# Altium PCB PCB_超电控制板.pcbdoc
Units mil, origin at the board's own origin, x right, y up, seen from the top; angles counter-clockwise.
Board outline 3640 x 2780 mil, 2 copper layers (Top Layer, Bottom Layer); 100 components, 60 nets, 308 pads, 246 vias.
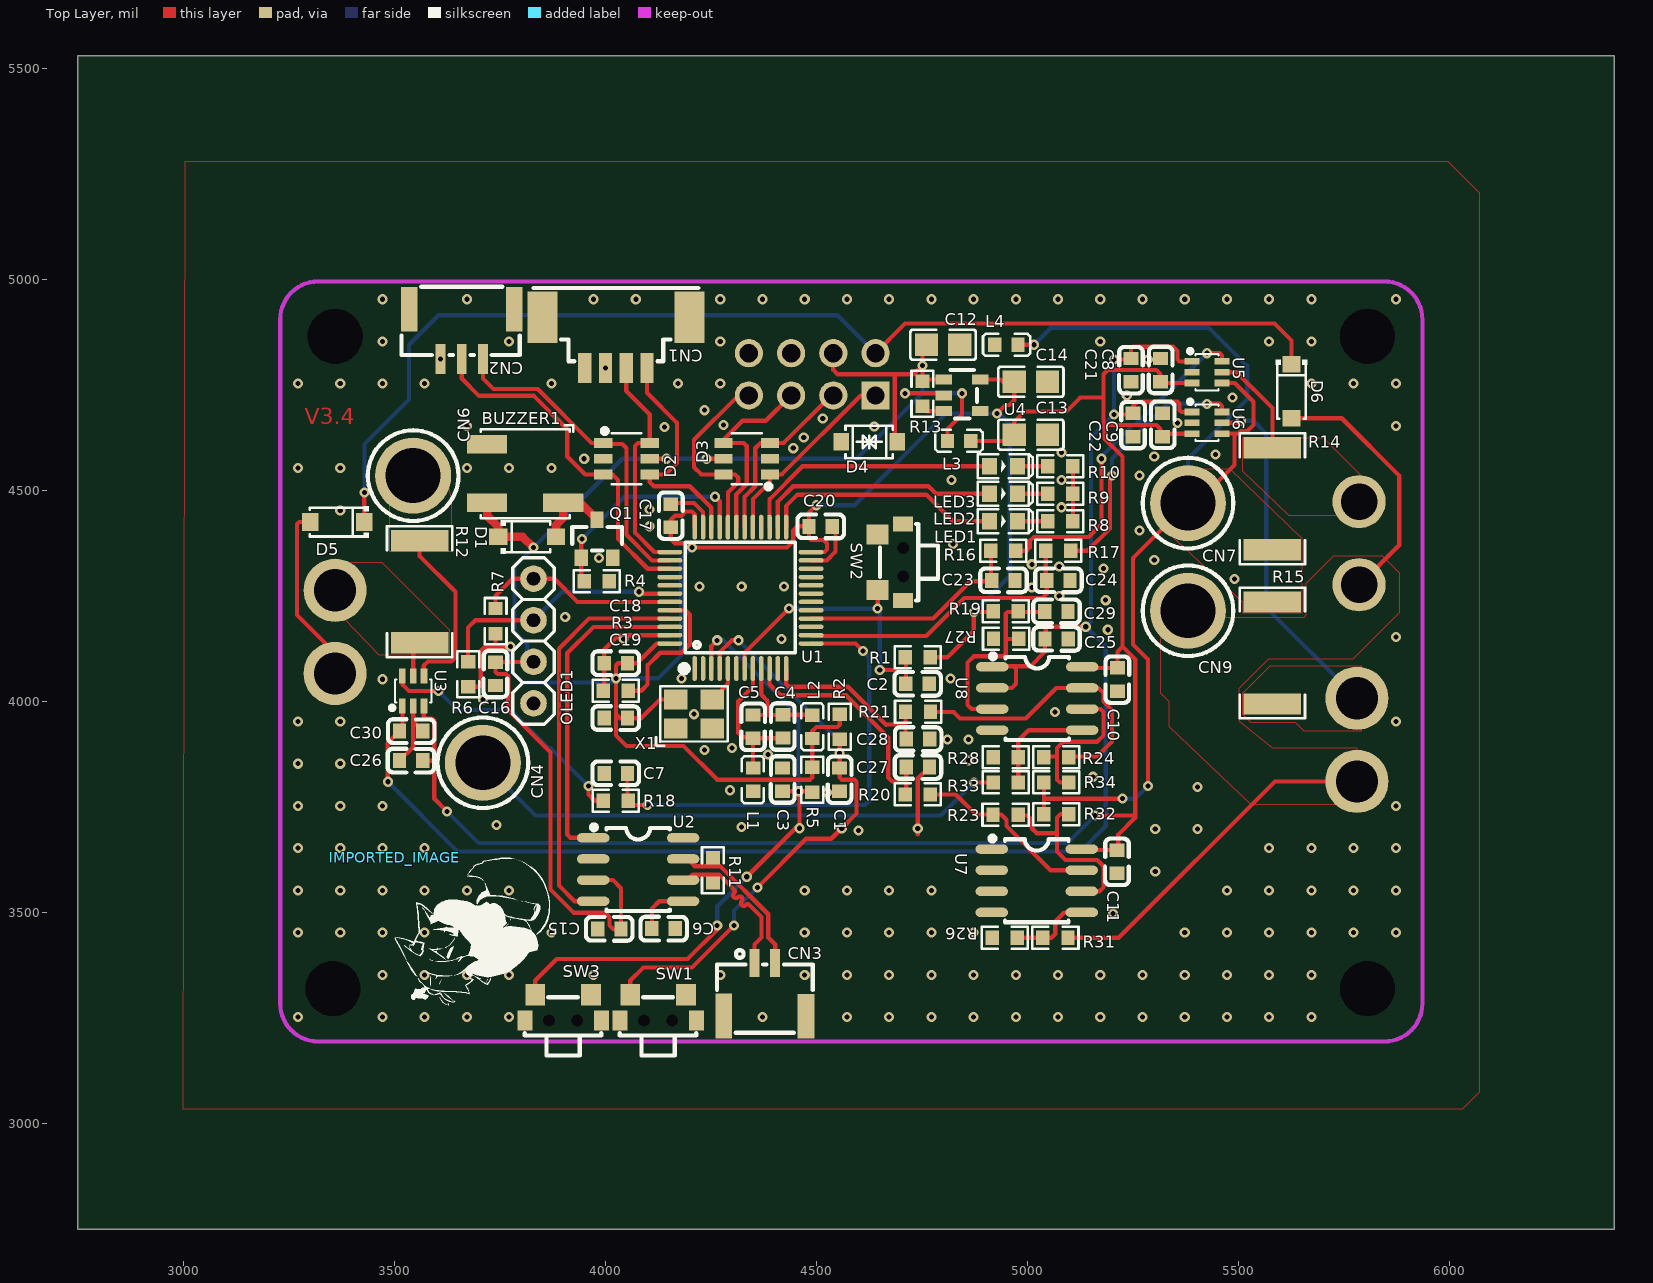
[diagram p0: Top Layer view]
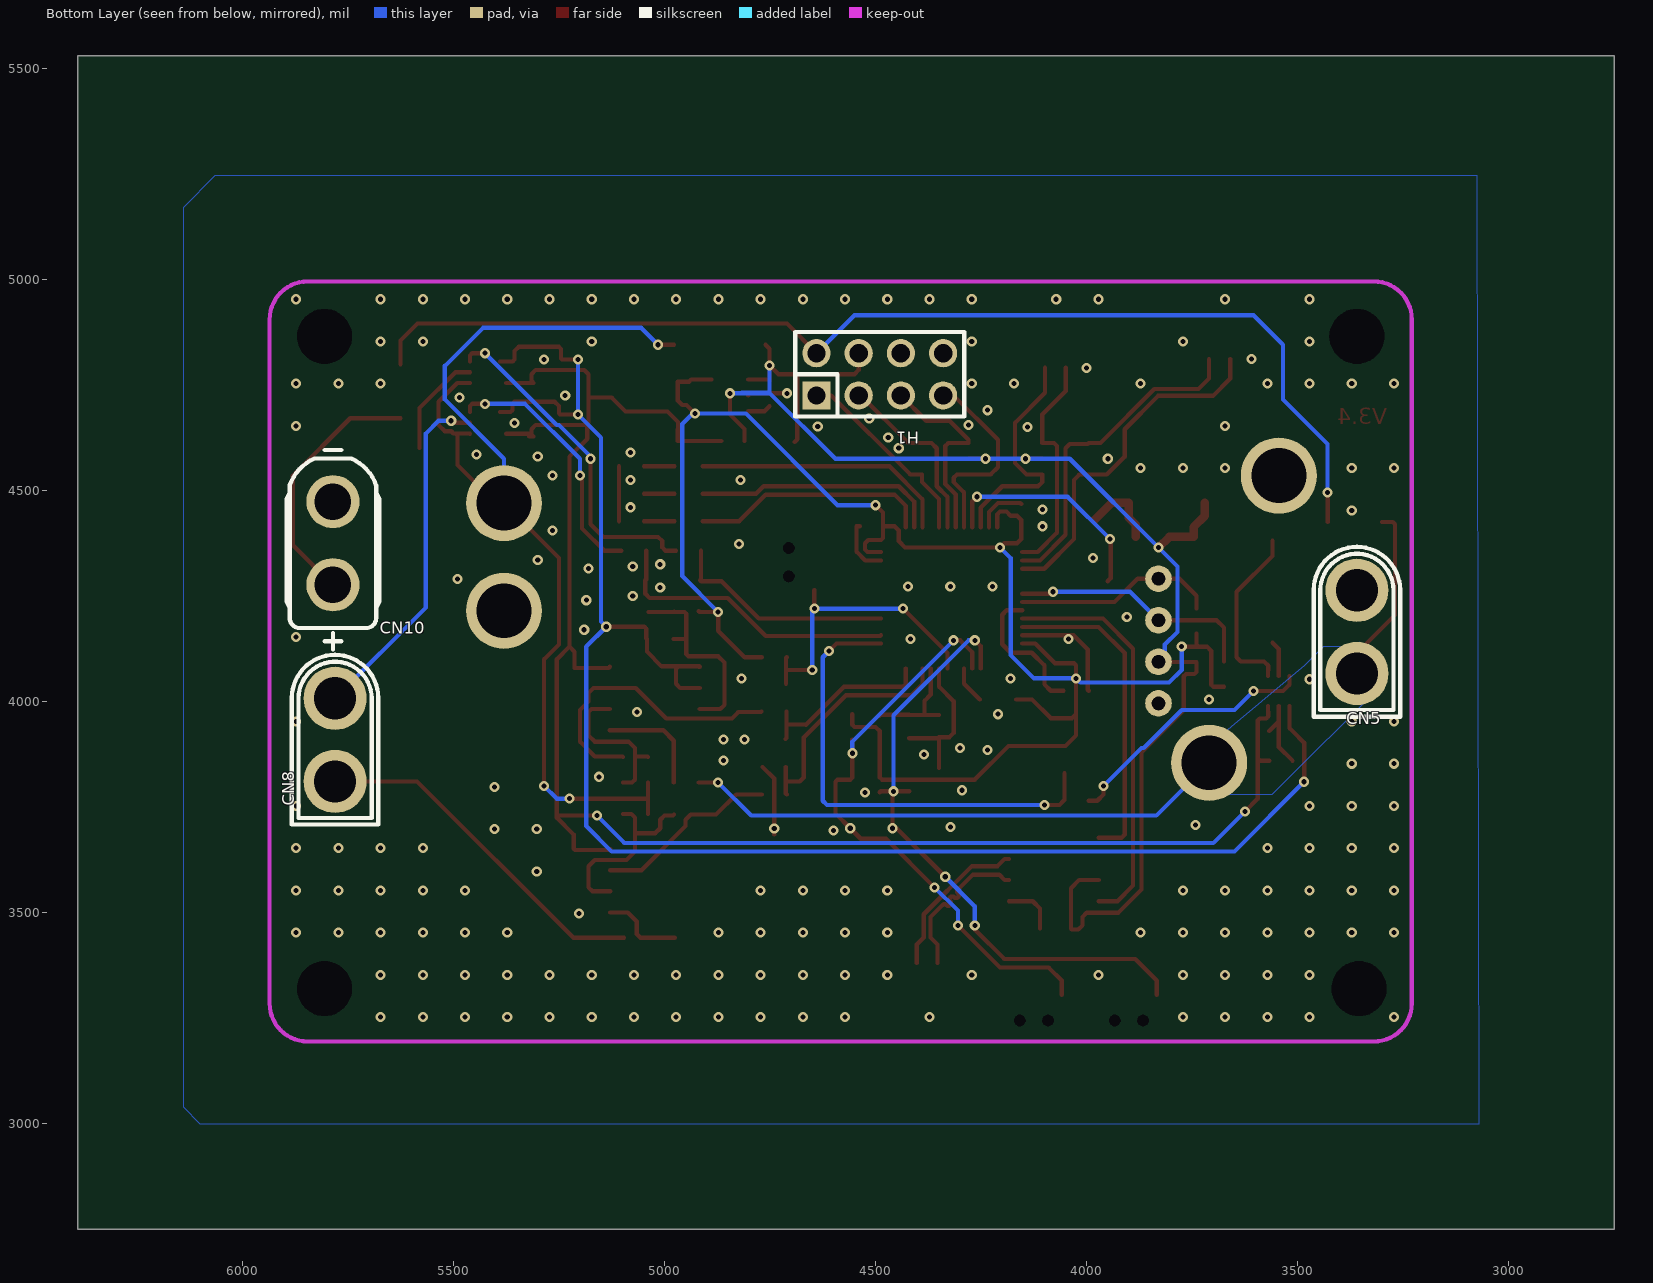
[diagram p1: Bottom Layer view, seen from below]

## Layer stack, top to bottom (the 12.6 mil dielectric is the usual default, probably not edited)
Top Layer: signal copper (thickness not stored)
Dielectric: dielectric 12.6, FR-4, Dk 4.8
Bottom Layer: signal copper (thickness not stored)

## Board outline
6390,2750 2750,2750 2750,5530 6390,5530
cut-out: 3420,3320 ccw(c3355,3320) 3290,3320 ccw(c3355,3320)
cut-out: 3425,4865 ccw(c3360,4865) 3295,4865 ccw(c3360,4865)
cut-out: 5870,4865 ccw(c5805,4865) 5740,4865 ccw(c5805,4865)
cut-out: 5870,3320 ccw(c5805,3320) 5740,3320 ccw(c5805,3320)

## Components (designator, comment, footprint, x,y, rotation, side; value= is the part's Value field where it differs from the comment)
BUZZER1 "MLT-5020" BUZ-SMD_3P-L5.2-W5.2-P3.50-BR 3810,4540 r90 top
C1 "1nf" C0603 4555,3815 r90 top
C2 "1uf" C0603 4739.39,4042.16 r180 top
C3 "1nf" C0603 4420,3815 r270 top
C4 "1nf" C0603 4420.4,3941 r90 top
C5 "0.1uf" C0603 4350,3940.7 r90 top
C6 "0.1uf" C0603 4137.8,3462.2 r180 top
C7 "330pF" C0603 4025,3830 r0 top
C8 "0.1u" C0603 5315,4785 r270 top
C9 "0.1u" C0603 5320,4655 r270 top
C10 "0.1u" C0603 5212.8,4052.2 r90 top
C11 "0.1u" C0603 5211.79,3620.61 r90 top
C12 "22u" C0805 4800,4845 r0 top
C13 "22u" C0805 5007.8,4632.2 r0 top
C14 "22u" C0805 5007.8,4757.2 r0 top
C15 "0.1u" C0603 4009.5,3461.7 r0 top
C16 "0.1u" C0603 3740,4065.7 r90 top
C17 "0.1u" C0603 4155,4440 r270 top
C18 "0.1u" C0603 4025,4090.7 r0 top
C19 "0.1u" C0603 4025,3960.7 r0 top
C20 "0.1u" C0603 4510,4415 r180 top
C21 "0.1u" C0603 5245,4785 r90 top
C22 "0.1u" C0603 5250,4655 r90 top
C23 "330pF" C0603 4942.8,4287.2 r180 top
C24 "330pF" C0603 5072.8,4287.2 r180 top
C25 "330pF" C0603 5069,4148.4 r0 top
C26 "0.1u" C0603 3540,3860 r0 top
C27 "330pF" C0603 4740,3845 r180 top
C28 "330pF" C0603 4740.56,3911.24 r180 top
C29 "330pF" C0603 5068.2,4213.7 r180 top
C30 "0.1u" C0603 3540,3930 r180 top
CN1 "1.25-4PWB" CONN-SMD_1.25-4PWB 4025,4850 r180 top
CN2 "GH1.25-3PWBPZ" CONN-SMD_GH1.25-3PWBPZ 3660,4870 r180 top
CN3 "GH1.25-2PWBPZ" CONN-SMD_GH1.25-2PWBPZ 4377.79,3317.89 r0 top
CN4 "m3焊盘" M3焊盘 3710,3855 r90 top
CN5 "XT30U-M" CONN-TH_XT30U-M 3360.01,4165 r90 bottom
CN6 "m3焊盘" M3焊盘 3545,4535 r90 top
CN7 "m3焊盘" M3焊盘 5380,4470 r0 top
CN8 "XT30U-M" CONN-TH_XT30U-M 5780.01,3909.3 r90 bottom
CN9 "m3焊盘" M3焊盘 5380,4215 r0 top
CN10 "XT30" CONN-TH_XT30UPB-F 5785.02,4375 r90 bottom
D1 "贴片二极管/JSPI3100A/SOD-123FL[捷捷微]" SOD-123F_L2.7-W1.6-LS3.8-RD 3815,4390 r0 top
D2 "IP4220CZ6" SOT-23-6_L2.9-W1.6-P0.95-LS2.7-BL 4050,4575 r270 top
D3 "IP4220CZ6" SOT-23-6_L2.9-W1.6-P0.95-LS2.7-BL 4335,4575 r90 top
D4 "SMFJ5.0CA" SOD-123_L2.8-W1.8-LS3.7-BI 4625,4615 r180 top
D5 "DSK310_C713648" SOD-123_L2.7-W1.8-LS3.7-RD 3365,4425 r180 top
D6 "DSK310_C713648" SOD-123_L2.7-W1.8-LS3.7-RD 5625,4735 r270 top
H1 "PZ254V-12-8P" HDR-TH_8P-P2.54-V-M-R2-C4-S2.54 4490,4775 r180 bottom
IMPORTED_IMAGE "IMPORTED_IMAGE" IMPORTED_IMAGE 3501,3630 r0 top
L1 "1m" L0603 4350,3815 r90 top
L2 "1m" L0603 4490.03,3940 r270 top
L3 "1m" L0603 4837.82,4617.2 r0 top
L4 "1m" L0603 4950,4845 r180 top
LED1 "LED-0603_R" LED0603_RED 4942.8,4427.2 r0 top
LED2 "LED-0603_G" LED0603_RED 4942.83,4492.17 r0 top
LED3 "LED-0603_B" LED0603_RED 4942.83,4557.17 r0 top
OLED1 "0.96OLED_4P_MODULE_JX" 排针2.54单排4PIN 3830,3995.68 r90 top
Q1 "2N7002" SOT-23_L2.9-W1.3-P0.95-LS2.4-BR 3980.53,4385.52 r270 top
R1 "10k" R0603 4740,4105 r180 top
R2 "10k" R0603 4555,3940 r90 top
R3 "1k" R0603 4025,4025.7 r180 top
R4 "10k" R0603 3980,4285 r180 top
R5 "10k" R0603 4490,3815 r90 top
R6 "10k" R0603 3675,4065 r90 top
R7 "10k" R0603 3740,4190.68 r90 top
R8 "100" R0603 5077.8,4427.2 r0 top
R9 "100" R0603 5077.8,4492.2 r0 top
R10 "100" R0603 5077.8,4557.2 r0 top
R11 "120" R0603 4255,3600 r270 top
R12 "2mΩ" R2512 3560,4260 r270 top
R13 "10k" R0603 4751.1,4728.9 r90 top
R14 "2mΩ" R2512 5580,4480 r90 top
R15 "2mΩ" R2512 5580,4115 r270 top
R16 "100" R0603 4942.8,4357.2 r0 top
R17 "100" R0603 5072.8,4357.2 r0 top
R18 "100" R0603 4025,3765 r180 top
R19 "2k" R0603 4948.2,4213.7 r0 top
R20 "100" R0603 4740,3780 r0 top
R21 "100" R0603 4740.56,3976.24 r0 top
R23 "3k3" R0603 4947.8,3732.2 r0 top
R24 "3k3" R0603 5068.3,3868.4 r180 top
R26 "3k3" R0603 4946.09,3440.61 r0 top
R27 "2k" R0603 4949,4148.4 r180 top
R28 "3k3" R0603 4948.3,3868.4 r0 top
R31 "68k" R0603 5066.09,3440.61 r180 top
R32 "68k" R0603 5068.3,3733.4 r180 top
R33 "68k" R0603 4948.3,3808.4 r0 top
R34 "68k" R0603 5068.3,3808.4 r0 top
SW1 "TS24CA" SW-SMD_TS24CA#1 4125,3275 r180 top
SW2 "TS24CA" SW-SMD_TS24CA#2 4675,4330 r270 top
SW3 "TS24CA" SW-SMD_TS24CA#1 3899.96,3275.01 r180 top
U1 "STM32F334C8T6" LQFP-48_L7.0-W7.0-P0.50-LS9.0-BL 4320,4245.68 r0 top
U2 "TJA1050T/CM,118" SOIC-8_L5.0-W4.0-P1.27-LS6.0-BL 4077.8,3602.2 r270 top
U3 "INA199A2DCKR" SOT-363_L2.0-W1.3-P0.65-LS2.1-BR 3545,4025 r270 top
U4 "RT9193-33" SOT-23-5_L2.9-W1.6-P0.95-LS2.8-BL 4845,4725 r270 top
U5 "INA199A2DCKR" SOT-363_L2.0-W1.3-P0.65-LS2.1-BR 5424.99,4780.01 r180 top
U6 "INA199A2DCKR" SOT-363_L2.0-W1.3-P0.65-LS2.1-BR 5424.99,4660.01 r180 top
U7 "GS8552-SR" SOIC-8_L5.0-W4.0-P1.27-LS6.0-BL 5021.79,3575.61 r270 top
U8 "GS8552-SR" SOIC-8_L5.0-W4.0-P1.27-LS6.0-BL 5022.8,4007.2 r270 top
X1 "8MHz" OSC-SMD_4P-L3.2-W2.5-BL 4210,3970.68 r0 top

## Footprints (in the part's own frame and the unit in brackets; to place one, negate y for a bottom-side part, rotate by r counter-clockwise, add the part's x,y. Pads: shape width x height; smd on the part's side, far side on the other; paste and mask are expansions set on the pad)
BUZ-SMD_3P-L5.2-W5.2-P3.50-BR [mm]
  rect 1.12x2.425 smd paste+0 mask+0.051: 1(1.75,2.288) 2(-1.75,2.288) 3(-1.75,-2.288)
  silkscreen extent -2.68,-2.9 2.9,2.68
C0603 [mm]
  rect 0.8x0.9 smd paste+0 mask+0.051: 1(-0.7,0) 2(0.7,0)
  silkscreen extent -1.41,-0.71 1.39,0.72
C0805 [mm]
  rect 1.41x1.35 smd paste-100 mask+0.051: 1(-1,0) 2(1,0)
  silkscreen extent -1.96,-0.9 1.96,0.9
CONN-SMD_1.25-4PWB [mm]
  rect 0.8x1.8 smd paste+0 mask+0.05: 1(-1.875,1.516) 2(-0.625,1.516) 3(0.625,1.516) 4(1.875,1.516)
  rect 1.8x3.1 smd paste+0 mask+0.05: 5(-4.425,-1.516) 6(4.425,-1.516)
  silkscreen extent -4.95,-3.28 4.95,1.12
CONN-SMD_GH1.25-2PWBPZ [mm]
  rect 0.6x1.7 smd paste+0 mask+0.051: 1(-0.625,1.602) 2(0.625,1.602)
  rect 1x2.7 smd paste+0 mask+0.051: 3(2.475,-1.602) 4(-2.475,-1.598)
  silkscreen extent -2.88,-2.6 2.88,2.37
CONN-SMD_GH1.25-3PWBPZ [mm]
  rect 0.6x1.8 smd paste+0 mask+0.05: 1(-1.27,1.501) 2(0,1.501) 3(1.27,1.501)
  rect 1x2.7 smd paste+0 mask+0.05: 4(-3.164,-1.501) 5(3.164,-1.501)
  silkscreen extent -3.49,-2.85 3.62,1.25
CONN-TH_XT30U-M [mm]
  round 3.8 hole 2.54 paste+0 mask+0.05: 1(-2.5,0) 2(2.5,0)
  silkscreen extent -5.1,-2.6 5.11,2.6
CONN-TH_XT30UPB-F [mm]
  round 3.2 hole 2.2 paste+0 mask+0.051: 1(-2.5,0) 2(2.5,0)
  silkscreen extent -6.4,-2.8 5.6,2.8
HDR-TH_8P-P2.54-V-M-R2-C4-S2.54 [mm]
  rect 1.7x1.7 hole 1.1 paste+0 mask+0.051: 1(-3.81,-1.27)
  round 1.7 hole 1.1 paste+0 mask+0.051: 2(-3.81,1.27) 3(-1.27,-1.27) 4(-1.27,1.27) 5(1.27,-1.27) 6(1.27,1.27) 7(3.81,-1.27) 8(3.81,1.27)
  silkscreen extent -5.08,-2.54 5.08,2.54
IMPORTED_IMAGE [mil]
  silkscreen extent 0,-350 368,0
L0603 [mm]
  rect 0.8x0.864 smd paste-100 mask+0.051: 1(-0.7,0) 2(0.7,0)
  silkscreen extent -1.42,-0.65 1.41,0.67
LED0603_RED [mm]
  rect 0.9x1 smd paste+0 mask+0.051: 1(-0.85,0) 2(0.85,0)
  silkscreen extent -1.54,-0.73 1.75,0.73
LQFP-48_L7.0-W7.0-P0.50-LS9.0-BL [mm]
  oval 0.27x1.5 smd paste+0 mask+0.05: 1(-2.75,-4.25) 2(-2.25,-4.25) 3(-1.75,-4.25) 4(-1.25,-4.25) 5(-0.75,-4.25) 6(-0.25,-4.25) 7(0.25,-4.25) 8(0.75,-4.25) 9(1.25,-4.25) 10(1.75,-4.25) 11(2.25,-4.25) 12(2.75,-4.25) 25(2.75,4.25) 26(2.25,4.25) 27(1.75,4.25) 28(1.25,4.25) 29(0.75,4.25) 30(0.25,4.25) 31(-0.25,4.25) 32(-0.75,4.25) 33(-1.25,4.25) 34(-1.75,4.25) 35(-2.25,4.25) 36(-2.75,4.25)
  oval 1.5x0.27 smd paste+0 mask+0.05: 13(4.25,-2.75) 14(4.25,-2.25) 15(4.25,-1.75) 16(4.25,-1.25) 17(4.25,-0.75) 18(4.25,-0.25) 19(4.25,0.25) 20(4.25,0.75) 21(4.25,1.25) 22(4.25,1.75) 23(4.25,2.25) 24(4.25,2.75) 37(-4.25,2.75) 38(-4.25,2.25) 39(-4.25,1.75) 40(-4.25,1.25) 41(-4.25,0.75) 42(-4.25,0.25) 43(-4.25,-0.25) 44(-4.25,-0.75) 45(-4.25,-1.25) 46(-4.25,-1.75) 47(-4.25,-2.25) 48(-4.25,-2.75)
  silkscreen extent -3.59,-4.46 3.3,3.34
M3焊盘 [mil]
  round 180 hole 130 paste+0 mask+1.97: 1(0.01,0)
  silkscreen extent -107,-107 107,107
OSC-SMD_4P-L3.2-W2.5-BL [mm]
  rect 1.4x1.2 smd paste+0 mask+0.051: 1(-1.1,-0.875) 2(1.1,-0.875) 3(1.1,0.875) 4(-1.1,0.875)
  silkscreen extent -2.29,-1.9 2.03,1.65
R0603 [mil]
  rect 31.75x34.02 smd paste-3937.01 mask+2: 1(-29.66,0) 2(29.66,0)
  silkscreen extent -55,-26 55,26
R2512 [mil]
  rect 50.49x136.06 smd paste-3937.01 mask+2: 1(-120.72,0) 2(120.72,0)
  silkscreen extent -155,-77 155,77
SOD-123_L2.7-W1.8-LS3.7-RD [mm]
  rect 1x1.1 smd paste+0 mask+0.051: 1(-1.627,0) 2(1.627,0)
  silkscreen extent -1.9,-0.94 1.65,0.95
SOD-123_L2.8-W1.8-LS3.7-BI [mm]
  rect 0.93x1.06 smd paste+0 mask+0.051: 1(1.685,0) 2(-1.685,0)
  silkscreen extent -1.43,-0.98 1.43,0.98
SOD-123F_L2.7-W1.6-LS3.8-RD [mm]
  rect 1.1x1 smd paste+0 mask+0.051: 1(-1.735,0) 2(1.735,0)
  silkscreen extent -1.6,-1 1.38,1
SOIC-8_L5.0-W4.0-P1.27-LS6.0-BL [mil]
  oval 22.38x76.78 smd paste+0 mask+2: 1(-75,-106.5) 2(-25,-106.5) 3(25,-106.5) 4(75,-106.5) 5(75,106.5) 6(25,106.5) 7(-25,106.5) 8(-75,106.5)
  silkscreen extent -106,-111 98,75
SOT-23-5_L2.9-W1.6-P0.95-LS2.8-BL [mm]
  rect 0.6x1 smd paste+0 mask+0.05: 1(-0.95,-1.1) 2(0,-1.1) 3(0.95,-1.1) 4(0.95,1.1) 5(-0.95,1.1)
  silkscreen extent -1.52,-0.7 1.4,0.89
SOT-23-6_L2.9-W1.6-P0.95-LS2.7-BL [mm]
  rect 0.6x1.1 smd paste+0 mask+0.051: 1(-0.95,-1.4) 2(0,-1.4) 3(0.95,-1.4) 4(0.95,1.4) 5(0,1.4) 6(-0.95,1.4)
  silkscreen extent -1.82,-1.45 1.54,0.89
SOT-23_L2.9-W1.3-P0.95-LS2.4-BR [mm]
  rect 1x0.8 smd paste+0 mask+0.051: 1(1.15,-0.95) 2(1.15,0.95) 3(-1.15,0)
  silkscreen extent -0.7,-1.5 0.7,1.5
SOT-363_L2.0-W1.3-P0.65-LS2.1-BR [mm]
  rect 0.9x0.4 smd paste+0 mask+0.051: 1(0.9,-0.65) 2(0.9,0) 3(0.9,0.65) 4(-0.9,0.65) 5(-0.9,0) 6(-0.9,-0.65)
  silkscreen extent -0.7,-1.4 1.14,1.1
SW-SMD_TS24CA#1 [mm]
  rect 0.9x1.2 smd paste+0 mask+0.051: 1(-2.3,0.775) 2(2.3,0.775)
  rect 1.2x1.3 smd paste+0 mask+0.051: 3(-1.675,-0.775) 4(1.675,-0.775)
  Multi-Layer board cut-out: -1.2,0.775 -1.165,0.623 -1.068,0.501 -0.928,0.434 -0.772,0.434 -0.632,0.501 -0.535,0.623 -0.5,0.775 -0.5,0.775 -0.535,0.927 -0.632,1.049 -0.772,1.116 -0.928,1.116 -1.068,1.049 -1.165,0.927 -1.2,0.775
  Multi-Layer board cut-out: 0.5,0.775 0.535,0.623 0.632,0.501 0.772,0.434 0.928,0.434 1.068,0.501 1.165,0.623 1.2,0.775 1.2,0.775 1.165,0.927 1.068,1.049 0.928,1.116 0.772,1.116 0.632,1.049 0.535,0.927 0.5,0.775
  silkscreen extent -2.3,-0.62 2.3,2.88
SW-SMD_TS24CA#2 [mm]
  rect 0.9x1.2 smd paste+0 mask+0.051: 1(-2.3,0.775) 2(2.3,0.775)
  rect 1.2x1.3 smd paste+0 mask+0.051: 3(-1.675,-0.775) 4(1.675,-0.775)
  Multi-Layer board cut-out: -0.85,1.125 -1.002,1.09 -1.124,0.993 -1.191,0.853 -1.191,0.697 -1.124,0.557 -1.002,0.46 -0.85,0.425 -0.85,0.425 -0.698,0.46 -0.576,0.557 -0.509,0.697 -0.509,0.853 -0.576,0.993 -0.698,1.09 -0.85,1.125
  Multi-Layer board cut-out: 0.85,1.125 0.698,1.09 0.576,0.993 0.509,0.853 0.509,0.697 0.576,0.557 0.698,0.46 0.85,0.425 0.85,0.425 1.002,0.46 1.124,0.557 1.191,0.697 1.191,0.853 1.124,0.993 1.002,1.09 0.85,1.125
  silkscreen extent -2.3,-0.62 2.3,2.88
排针2.54单排4PIN [mm]
  round 1.6 hole 0.8 slot 0.805 at 0 deg paste+0 mask+0.051: 1(0,0) 2(2.5,0) 3(5,0) 4(7.5,0)
  silkscreen extent -1.25,-1.25 8.75,1.25

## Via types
v1: diameter 24, hole 12, Top Layer to Bottom Layer, 242 vias
v2: diameter 24.02, hole 12.01, Top Layer to Bottom Layer, 4 vias

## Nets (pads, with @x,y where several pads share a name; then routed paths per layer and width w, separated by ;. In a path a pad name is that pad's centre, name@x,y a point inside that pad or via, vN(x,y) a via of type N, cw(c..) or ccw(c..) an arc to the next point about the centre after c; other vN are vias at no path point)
1.65V: C21.2 C22.2 C25.1 C30.2 U3.1 U5.1 U6.1 U8.1 U8.2 | length 4023.6
  Top Layer w10: v1(3485,3810) 3485,3902.56 C30.2 3519.41,3936.97 U3.1 ; U8.2 4962.8,4032.2 4972.8,4042.2 4972.8,4077.2 4966.56,4083.44 U8.1@4917.54,4083.44 ; U8.1 U8.1@4918.8,4082.2 ; 4966.6,4083.4 5006.6,4083.4 5041.5,4118.4 5041.5,4148.4 5042.8,4149.8 5042.8,4172.2 5047.8,4177.2 v1(5137.8,4177.2) ; v1(5205,4680) 5247.44,4680 C22.2 ; v1(5205,4810) 5242.44,4810 C21.2 5245,4835 5250,4840 5345,4840 5355,4830 5355,4810 5359.41,4805.59 U5.1 ; C22.2 5250,4700 5260,4710 5355,4710 5360,4705 5360,4690 5364.4,4685.6 ; 5364.4,4685.6 U6.1 5369.4,4685.6 5364.4,4685.6
  Bottom Layer w10: v1(3485,3810) 3650,3645 5125,3645 5185,3705 5185,4130 v1(5137.8,4177.2) 5150,4189.4 5150,4625 v1(5205,4680) v1(5205,4810)
3V3: C14.1 C17.2 C18.2 C19.2 C20.2 L2.2 R1.1 R2.2 R5.2 R6.1 R7.1 R19.1 U1.24 U1.36 U1.48 U4.5 X1.4 | length 4319.3
  Top Layer w10: R6.1 3699.7,4035.3 3705,4040 3705,4120 3715,4130 3735,4130 ; R7.1 3740,4135 3735,4130 ; v1(3775,4130) 3735,4130 ; U1.48 4121.7,4137.4 4075,4090.7 C18.2 4030,4090.7 4025,4085.7 4025,3970.7 ; X1.4 4129.4,4005.1 4085,3960.7 C19.2 4035,3960.7 4025,3970.7 ; U1.36 4211.7,4443.3 4205,4450 4190,4450 4180,4440 4165,4440 4155,4430 C17.2 4155,4385 4165,4375 4195,4375 v1(4205,4365) 4430,4365 4445,4380 4445,4405 4455,4415 C20.2 4482.44,4447.44 v1(4500,4465) ; C20.2 4482.4,4387.6 4487.4,4382.6 4517.4,4382.6 4525,4375 4525,4360 4519,4354 U1.24 ; R2.2 4555,3945 4550,3940 4500,3940 4490,3930 L2.2 R5.2 4490,3820 4485,3815 4265,3815 4185,3895 4050,3895 4025,3920 4025,3970.7 ; R1.1 4810,4105 4872.8,4167.8 v1(4872.8,4212.2) 4917.13,4212.2 R19.1@4918.58,4213.65 ; U4.5 4936.73,4762.4 4941.93,4757.2 C14.1 4968.43,4712.83 4957.8,4702.2 4947.8,4702.2 v1(4927.8,4682.2)
  Bottom Layer w10: v1(3775,4130) 3775,4075 3805,4045 4015,4045 v1(4025,4055) 4125,4055 4180,4110 4180,4340 v1(4205,4365) ; v1(4500,4465) 4590,4465 4807.2,4682.2 v1(4927.8,4682.2) 4932.8,4682.2 4957.8,4657.2 4957.8,4297.2 v1(4872.8,4212.2)
+5V: BUZZER1.2 C12.1 C15.2 C16.2 D1.1 D2.5 D3.5 D4.2 H1.4 L3.1 OLED1.2 R13.2 U2.3 U4.1 | length 3653
  Top Layer w10: C16.2@3740,4093.2 3740,4070 3745,4065 3765,4065 3770,4060 3770,3980 3870,3880 3870,3555 3925,3500 4000,3500 4010,3490 4010,3470 4020,3460 4035.36,3460 C15.2 ; C16.2 OLED1.2 ; U2.3 4017.8,3577.2 4037.11,3557.9 C15.2 ; D2.5 v1(4145,4575) ; v1(4240,4575) D3.5 ; H1.4 4540,4785 4550,4775 4730,4775 v1(4751.1,4796.1) ; 4685.34,4775 4685.34,4621 D4.2 ; R13.2 4751.1,4835.47 C12.1 ; R13.2 4754.9,4762.4 U4.1 ; L3.1@4810.2,4617.2 4810.2,4645.2 4845,4680 v1(4845,4730)
  Top Layer w20: BUZZER1.2 3719.9,4440.1 3746.7,4413.3 D1.1 3804.05,4390 v1(3829.53,4364.53)
  Bottom Layer w10: OLED1.2 3815,4109.1 3815,4135 3785,4165 3785,4320 v1(3829.53,4364.53) 4040,4575 v1(4145,4575) v1(4240,4575) ; v1@4238.65,4575 v1(4240,4575) ; v1(4751.1,4796.1) 4751.1,4730 v1(4845,4730) ; 4817.2,4730 4816.1,4731.1 4751.1,4731.1 4595,4575 v1(4240,4575)
ADC_ICUP: C7.2 R18.1 U1.13 | length 1135.6
  Top Layer w10: C7.2 4052.56,3767.1 R18.1 4064.66,3755 v1(4100,3755) ; U1.13 4592.59,4137.41 v1(4610,4120)
  Bottom Layer w10: v1(4100,3755) 4615,3755 4625,3765 4625,4105 v1(4610,4120)
ADC_IIN: C24.2 R17.1 U1.14 | length 703.1
  Top Layer w10: U1.14 4489.4,4155 4760,4155 4850,4245 5035,4245 5045.2,4255.2 C24.2 ; R17.1 5043.14,4289.3 C24.2
ADC_IOUT: C23.2 R16.1 U1.16 | length 537.6
  Top Layer w10: U1.16 4776.5,4196.5 4865,4285 4913,4285 C23.2 4913.1,4287.2 R16.1
ADC_VCC: C27.2 R20.1 U1.10 | length 575.8
  Top Layer w10: U1.10 4388.9,4041.1 4415,4015 4570,4015 4670,3915 4670,3820 4679.5,3810.5 4710.4,3810.5 ; R20.1 4712.44,3782.1 C27.2
ADC_VCUP: C28.2 R21.1 U1.12 | length 425.2
  Top Layer w10: U1.12 4428.3,4041.7 4435,4035 4575,4035 4665,3945 4710.9,3945.6 ; R21.1@4710.94,3976.28 4710.94,3913.38 C28.2@4713.05,3911.28
AVCC: C8.2 C9.2 C10.2 C11.2 C13.1 C26.2 L3.2 U3.3 U5.3 U6.3 U7.8 U8.8 | length 4253.9
  Top Layer w10: C26.2 3590,3860 3595,3865 ; U3.3 3570,3965 3575,3960 3590,3960 3595,3955 3595,3865 ; v1(3625,3740) 3595,3770 3595,3865 ; L3.2 4968.4,4617.2 C13.1 4967.8,4662.2 4992.8,4687.2 5092.2,4687.2 5125,4720 5180,4720 ; U7.8 5130.77,3648.21 C11.2 ; U8.8 5131.74,4079.76 C10.2 ; v1(5160,3730) 5250,3730 5255,3725 ; 5182.8,4657.2 5182.8,4622.2 5225,4580 5225,4130 ; C11.2 5215,3651.38 5215,3685 5255,3725 ; C10.2 5212.8,4117.8 5225,4130 ; 5225,4136.9 5225,4130 ; C8.2@5310,4754.4 5313.04,4757.44 C8.2 5315,4754.4 U5.3@5374.57,4754.4 ; C9.2@5315,4627.4 5315,4645 5305,4655 5185,4655 5180,4660 5180,4720 ; C8.2 5315,4775 5305,4785 5190,4785 5180,4775 5180,4720 ; C9.2 5310,4627.44 5316.96,4634.4 U6.3@5374.57,4634.4 ; 5225,4130 5255,4100 5255,3725
  Bottom Layer w10: v1(3625,3740) 3700,3665 5095,3665 v1(5160,3730)
BUZZER: Q1.1 R4.2 U1.33 | length 536.7
  Top Layer w10: v1(3945,4385) 3943.12,4383.12 Q1.1 3943.12,4292.22 R4.2 ; v1(4260,4485) 4270.79,4474.21 U1.33
  Bottom Layer w10: v1(3945,4385) 4045,4485 v1(4260,4485)
BUZZER1_3: BUZZER1.3 D1.2 Q1.3 | length 185.2
  Top Layer w20: D1.2 3883.3,4418.3 3900.1,4435.1 BUZZER1.3 ; BUZZER1.3 3940.22,4471.1 Q1.3
C4_1: C4.1 C5.1 L1.2 U1.8 | length 349.8
  Top Layer w10: U1.8 4349.5,4035.2 4315,4000.7 4315,3925.7 4325,3915.7 4350,3915.7 C5.1 4420.1,3913.1 C4.1 ; L1.2 C5.1
C6_2: C6.2 U2.5 | length 128.8
  Top Layer w10: C6.2 4110.24,3509.64 4127.8,3527.2 U2.5
C29_2: C29.2 R19.2 R27.1 U8.3 | length 479.7
  Top Layer w10: U8.3 4867.8,3982.2 4857.8,3992.2 4857.8,4092.2 4872.8,4107.2 4942.8,4107.2 4948.3,4112.7 4948.3,4207.7 4952.8,4212.2 4975.4,4212.2 R19.2@4976.6,4213.4 ; 4949.04,4148.44 R27.1 ; R19.2@4975.02,4212.2 C29.2@5037.8,4212.2
CAN_N: CN3.1 R11.2 U2.6 | length 377.5
  Top Layer w10: U2.6 4194.3,3577.2 4207.1,3590 4269.44,3590 4304.63,3554.77 cw(c4300.03,3550.18) 4304.63,3545.58 ccw(c4309.27,3541.03) 4313.82,3536.39 cw(c4318.42,3531.79) 4323.01,3536.39 cw(c4318.42,3531.79) 4323.01,3527.2 ccw(c4327.61,3522.6) 4332.21,3518 cw(c4336.8,3513.41) 4341.4,3518 4369.8,3489.65 4369.8,3441.05 4353.18,3424.43 CN3.1
CAN_P: CN3.2 R11.1 U2.7 | length 377.9
  Top Layer w10: U2.7 4194.3,3627.2 4211.31,3610.19 4251.31,3610.19 4271.86,3610.19 4385.78,3496.27 4385.78,3481.05 4385.78,3441.05 4402.4,3424.43 CN3.2
CAN_RX: U1.45 U2.4 | length 949.6
  Top Layer w10: U2.4 3927.2,3527.2 3890,3564.4 3890,4125 3961.5,4196.5 U1.45
CAN_TX: U1.46 U2.1 | length 762.8
  Top Layer w10: U2.1 3917.8,3677.2 3910,3685 3910,4115 3971.8,4176.8 U1.46
GND: BUZZER1.1 C1.1 C2.1 C3.1 C6.1 C7.1 C8.1 C9.1 C10.1 C11.1 C12.2 C13.2 C14.2 C15.1 C16.1 C17.1 C18.1 C19.1 C20.1 C21.1 C22.1 C23.1 C24.1 C25.2 C26.1 C27.1 C28.1 C29.1 C30.1 CN1.3 CN1.5 CN1.6 CN2.3 CN2.4 CN2.5 CN3.3 CN3.4 D2.2 D3.2 D4.1 H1.6 H1.8 L1.1 L4.2 OLED1.1 Q1.2 R3.2 R4.1 R8.2 R9.2 R10.2 R26.1 R27.2 R28.1 SW1.1 SW1.2 SW1.3 SW2.1 SW2.2 SW2.3 SW3.1 SW3.2 SW3.3 U1.23 U1.35 U1.47 U2.2 U2.8 U3.2 U4.2 U5.2 U6.2 U7.4 U8.4 X1.2 | length 1093.3
  Top Layer w10: C26.1 3545,3892.56 3545,3952.56 ; U3.2 3545,3952.56 ; C30.1 3545,3952.56 ; R3.2 3997.4,4027.8 C18.1 3997.4,4123.1 4031.4,4157.1 U1.47 ; C17.1 4157.44,4470 4210,4470 4231.42,4448.58 U1.35 ; U1.23 4524.3,4334.3 4545,4355 4545,4415 C20.1 ; v1(4710,4730) 4796.69,4730 U4.2 ; 4740,3685 v1(4740,3698.97) 4740,3817.44 C27.1 ; R8.2 R10.2
  other v1: 3272.2,3252.8 3272.2,3252.8 3472.2,3252.8 3572.2,3252.8 3672.2,3252.8 3772.2,3252.8 4372.2,3252.8 4572.2,3252.8 4672.2,3252.8 4772.2,3252.8 4872.2,3252.8 4972.2,3252.8 5072.2,3252.8 5172.2,3252.8 5272.2,3252.8 5372.2,3252.8 5472.2,3252.8 5572.2,3252.8 5672.2,3252.8 3472.2,3352.8 3572.2,3352.8 3672.2,3352.8 3772.2,3352.8 3972.2,3352.8 4272.2,3352.8 4472.2,3352.8 4572.2,3352.8 4672.2,3352.8 4772.2,3352.8 4872.2,3352.8 4972.2,3352.8 5072.2,3352.8 5172.2,3352.8 5272.2,3352.8 5372.2,3352.8 5472.2,3352.8 5572.2,3352.8 5672.2,3352.8 3272.2,3452.8 3372.2,3452.8 3472.2,3452.8 3572.2,3452.8 3672.2,3452.8 3772.2,3452.8 3872.2,3452.8 4472.2,3452.8 4572.2,3452.8 4672.2,3452.8 4772.2,3452.8 4872.2,3452.8 5372.2,3452.8 5472.2,3452.8 5572.2,3452.8 5672.2,3452.8 5772.2,3452.8 5872.2,3452.8 5202.36,3497.76 3272.2,3552.8 3372.2,3552.8 3472.2,3552.8 3572.2,3552.8 3672.2,3552.8 3772.2,3552.8 4472.2,3552.8 4572.2,3552.8 4672.2,3552.8 4772.2,3552.8 5472.2,3552.8 5572.2,3552.8 5672.2,3552.8 5772.2,3552.8 5872.2,3552.8 5302.36,3597.76 3272.2,3652.8 3372.2,3652.8 3472.2,3652.8 3572.2,3652.8 5572.2,3652.8 5672.2,3652.8 5772.2,3652.8 5872.2,3652.8 4600,3695 5302.36,3697.76 5402.36,3697.76 4322.2,3702.8 3742.2,3707.8 3272.2,3752.8 3372.2,3752.8 3472.2,3752.8 5872.2,3752.8 4525,3785 4295,3790 5402.36,3797.76 5155.14,3821.81 3272.2,3852.8 3372.2,3852.8 4860,3860 4385,3875 4235,3885 4300,3890 4810,3910 4860,3910 3272.2,3952.8 3372.2,3952.8 5872.2,3952.8 4210,3970 5065,3975 3710,4005 3472.2,4052.8 4817.67,4054.49 4180,4055 4417.67,4148.02 5872.2,4152.8 5190,4170 3905,4200 5185,4240 5075,4250 5010,4270 4223.01,4272.8 4323.01,4272.8 4423.01,4272.8 5180,4315 5075,4320 5010,4325 5300,4335 3985,4340 4823.01,4372.8 5265,4405 4105,4415 3372.2,4452.8 4105,4455 5080,4460 4820,4525 5080,4525 5265,4535 3272.2,4552.8 3372.2,4552.8 3672.2,4552.8 3772.2,4552.8 3872.2,4552.8 3950,4575 5300,4580 5445,4585 5080,4590 4445,4600 4470,4625 4140,4650 4636.98,4651.78 3672.2,4652.8 5872.2,4652.8 4280,4655 5355,4660 4515,4670 4235,4690 5485,4720 5235,4725 3272.2,4752.8 3372.2,4752.8 3472.2,4752.8 3572.2,4752.8 3872.2,4752.8 4172.2,4752.8 4272.2,4752.8 5672.2,4752.8 5772.2,4752.8 5872.2,4752.8 4000.4,4790.3 5285,4810 3610,4810.91 3472.2,4852.8 3772.2,4852.8 4272.2,4852.8 5172.2,4852.8 5572.2,4852.8 5672.2,4852.8 3472.2,4952.8 3672.2,4952.8 3972.2,4952.8 4072.2,4952.8 4272.2,4952.8 4372.2,4952.8 4472.2,4952.8 4572.2,4952.8 4672.2,4952.8 4772.2,4952.8 4872.2,4952.8 4972.2,4952.8 5072.2,4952.8 5172.2,4952.8 5272.2,4952.8 5372.2,4952.8 5472.2,4952.8 5572.2,4952.8 5672.2,4952.8 5872.2,4952.8
  other v2: 4042.68,4147.79
HRTIM1_CHA1: D3.1 H1.1 U1.29 | length 468.9
  Top Layer w10: U1.29 4349.53,4479.53 4390.12,4520.12 D3.1 4417.6,4537.6 4605,4725 H1.1
HRTIM1_CHA2: D3.3 H1.3 U1.30 | length 434.2
  Top Layer w10: U1.30 4329.84,4484.84 4355,4510 4355,4600 4367.4,4612.4 D3.3 4422.4,4612.4 4535,4725 H1.3
HRTIM1_CHB1: D3.4 H1.5 U1.31 | length 471.6
  Top Layer w10: U1.31 4310.16,4490.16 4335,4515 4335,4605 4327.6,4612.4 D3.4 4279.9,4619.9 4325,4665 4380,4665 H1.5
HRTIM1_CHB2: D3.6 H1.7 U1.32 | length 481
  Top Layer w10: U1.32 4290.5,4495.5 4315,4520 4315,4530 4307.4,4537.6 D3.6 4227.4,4537.6 4210,4555 4210,4620 4315,4725 H1.7
I2C_SCL: OLED1.3 R6.2 U1.42 | length 595
  Top Layer w10: R6.2 3675,4175 3692.5,4192.5 OLED1.3 ; v1(4080,4260) 4084.48,4255.52 U1.42
  Bottom Layer w10: OLED1.3 3897.5,4260 v1(4080,4260)
I2C_SDA: OLED1.4 R7.2 U1.43 | length 482.6
  Top Layer w10: R7.2 3740,4250.68 3780.28,4290.97 OLED1.4 ; OLED1.4 3879,4291 3934.2,4235.8 U1.43
KEY1: C1.2 R2.1 SW1.4 U1.4 | length 1424.5
  Top Layer w10: SW1.4 4059.05,3339.05 4090,3370 4205,3370 v1(4305,3470) ; U1.4 4270.8,4116.5 4299.3,4145 v2(4315,4145) ; v1(4360,3560) 4475,3675 4535,3675 v1(4560,3700) 4595,3735 4595,3810 4590,3815 4560,3815 4555,3820 C1.2 ; C1.2 v1(4555,3877.56) R2.1
  Bottom Layer w10: v1(4305,3470) 4305,3505 v1(4360,3560) ; v2(4315,4145) 4555,3905 v1(4555,3877.56)
KEY2: C3.2 R5.1 SW3.4 U1.3 | length 1527.9
  Top Layer w10: SW3.4@3834,3314 SW3.4 3834.01,3339.01 3885,3390 4195,3390 4265,3460 v1(4265,3470) ; U1.3 4251.1,4131.8 4264.3,4145 v2(4265,4145) ; v1(4335,3585) 4450,3700 v1(4460,3700) 4460,3784.87 v1(4457.43,3787.44) ; C3.2 v1(4457.43,3787.44) ; R5.1 4487.9,3787.44 v1(4457.43,3787.44)
  Bottom Layer w10: v1(4265,3470) 4265,3515 v1(4335,3585) ; v2(4265,4145) 4280,4145 4457.4,3967.6 v1(4457.43,3787.44)
L2_1: C4.2 C5.2 L2.1 U1.9 | length 257.7
  Top Layer w10: C5.2 C4.2 ; U1.9 4369.2,4016.5 4384,4001.7 4384,3968.4 ; C4.2@4420.4,3968.5 4487.5,3968.5 L2.1@4490.4,3965.6
LEDB: LED3.1 U1.27 | length 618.8
  Top Layer w10: U1.27 4388.9,4478.9 4467.17,4557.17 LED3.1
LEDG: LED2.1 U1.26 | length 595.4
  Top Layer w10: U1.26 4408.58,4473.58 4445,4510 4765,4510 4782.83,4492.17 LED2.1 ; LED2.1@4897.8,4492.2 LED2.1
LEDR: LED1.1 U1.25 | length 568.4
  Top Layer w10: U1.25 4428.27,4463.27 4455,4490 4760,4490 4822.8,4427.2 LED1.1
PGND: CN7.1 L4.1 R14.1 R15.1 R32.2 R34.1 U5.4 U6.4 | length 2520.3
  Top Layer w10: L4.1 v1(5015,4845) ; R32.2@5038.68,3733.44 R34.1@5038.68,3808.44 ; 5038.7,3769.9 v1(5225,3770) ; 5038.68,3771.88 5039,3772.2 ; v1(5285,3800) 5285,4100 5250,4135 5250,4340 CN7.1 ; CN7.1@5380,4450 5490,4560 5490,4630 5495,4635 5500,4635 ; U6.4 5500,4635 ; U5.4 5490.59,4754.41 5535,4710 5535,4655 5520,4640 5505,4640 5500,4635
  Bottom Layer w10: v1(5015,4845) 5055,4885 5430,4885 5520,4795 5520,4715 5380,4575 CN7.1 ; v1(5225,3770) 5255,3770 v1(5285,3800)
  other v1: 5490,4290
PGND_CUP: CN6.1 R12.1 U3.4 | length 418.8
  Top Layer w10: R12.1 3560,4345 3645,4260 3645,4105 3635,4095 3580,4095 3570,4085 U3.4
PGND_CUP_IN: CN5.2 R12.2 U3.5 | length 85.1
  Top Layer w10: U3.5 3545,4124.28 R12.2
PGND_IN: CN8.2 R15.2 U6.5 | length 835.4
  Top Layer w10: U6.5 5500.01,4660.01 v1(5505,4665)
  Bottom Layer w10: v1(5505,4665) 5535,4665 5565,4635 5565,4222.73 CN8.2
PGND_OUT: CN10.2 R14.2 U5.5 | length 249.1
  Top Layer w10: U5.5 5495,4780.01 5580,4695 R14.2
R3_1: R3.1 U1.44 | length 338.9
  Top Layer w10: R3.1 4085,4025.7 4100,4040.7 4100,4085.7 4130,4115.7 4180,4115.7 4200,4135.7 4200,4205.7 4189.5,4216.2 U1.44
R8_1: LED1.2 R8.1 | length 71.8
  Top Layer w10: LED1.2 R8.1
R9_1: LED2.2 R9.1 | length 71.8
  Top Layer w10: LED2.2 R9.1
R10_1: LED3.2 R10.1 | length 71.8
  Top Layer w10: LED3.2 R10.1
R13_1: R13.1 U4.3 | length 55.4
  Top Layer w10: R13.1@4751.09,4699.28 4762.77,4687.6 U4.3
R16_2: R16.2 U5.6 | length 800.4
  Top Layer w10: R16.2 4997.2,4357.2 5005,4365 5005,4380 5015,4390 5145,4390 5175,4420 v1(5175,4575) ; v1(5425,4825) 5455,4825 5460.42,4819.58 U5.6
  Bottom Layer w10: v1(5175,4575) 5175,4580 5250,4655 5255,4655 v1(5425,4825)
R20_2: R20.2 R23.1 U7.7 | length 441.7
  Top Layer w10: R20.2 4830,3780 4877.8,3732.2 R23.1 4937.8,3732.2 4950,3720 4950,3705 5054.4,3600.6 U7.7
R23_2: R23.2 R32.1 U7.6 | length 464.1
  Top Layer w10: R23.2 4979.66,3730 5000,3730 5010,3720 5010,3700 5021.95,3688.05 5070,3688.05 ; R32.1 5078.4,3733.4 5070,3725 5070,3645 5090,3625 5165,3625 5180,3610 5180,3560 5170.6,3550.6 U7.6
R24_1: R21.2 R24.1 U8.7 | length 691.9
  Top Layer w10: R21.2 4771.5,3975 4825,3975 4840,3960 4995.6,3960 5067.8,4032.2 U8.7 5167.8,4032.2 5180,4020 5180,4000 5200,3980 5200,3905 5165,3870 5099.56,3870 R24.1
R24_2: R24.2 R34.2 U8.6 | length 378.9
  Top Layer w10: R24.2 5040.2,3870 5070,3870 5070,3815 5076.6,3808.4 R34.2 ; 5070,3860 5070,3890 5085,3905 5165,3905 5180,3920 5180,3975 5172.8,3982.2 U8.6
R26_2: R26.2 R31.2 U7.5 | length 194.9
  Top Layer w10: R26.2 R31.2@5036.47,3440.65 ; R31.2@5036.49,3440.61 5056.79,3440.61 5065.59,3449.41 5065.59,3479.41 5086.79,3500.61 U7.5
RST: C2.2 R1.2 SW2.4 U1.7 | length 711.8
  Top Layer w10: U1.7 4329.8,4114.8 v2(4435,4220) ; SW2.4 4645,4263.54 v1(4645,4220) ; v1(4650,4075) 4711.8,4074.6 ; R1.2 4711.83,4103.51 C2.2
  Bottom Layer w10: v2(4435,4220) v1(4645,4220) 4650,4215 v1(4650,4075)
SWCLK: CN1.2 D2.6 U1.37 | length 545.8
  Top Layer w10: CN1.2 4049.6,4735.4 4105.1,4679.9 D2.6 4077.4,4612.4 4070,4605 4070,4400 4116,4354 U1.37
SWDIO: CN1.1 D2.4 U1.34 | length 565.9
  Top Layer w10: CN1.1 4098.8,4731.2 4170,4660 4170,4565 4142.6,4537.6 D2.4 4105,4520 4115,4510 4200,4510 4251.1,4458.9 U1.34
U3_6: R18.2 U3.6 | length 621.4
  Top Layer w10: U3.6 3520,4040 3535,4025 v1(3605,4025) ; v1(3960,3800) 3960,3780 3975,3765 R18.2
  Bottom Layer w10: v1(3605,4025) 3650,3980 3775,3980 3865,3890 3870,3890 v1(3960,3800)
U6_6: R17.2 U6.6 | length 611.9
  Top Layer w10: R17.2 5142.2,4357.2 5195,4410 5195,4530 v1(5200,4535) ; v1(5425,4705) 5455,4705 5460.4,4699.6 U6.6
  Bottom Layer w10: v1(5200,4535) 5200,4575 5330,4705 v1(5425,4705)
U8_5: R28.2 R33.2 U8.5 | length 260.7
  Top Layer w10: R33.2 R28.2 ; R28.2 4977.8,3907.2 5002.8,3932.2 U8.5
USART2_RX: CN2.1 D2.1 U1.38 | length 787.1
  Top Layer w10: CN2.1 3710,4765 3735,4740 3840,4740 3967.6,4612.4 D2.1 3997.28,4610 4040,4610 4050,4600 4050,4395 4110.74,4334.26 U1.38
USART2_TX: CN2.2 D2.3 U1.39 | length 845.2
  Top Layer w10: CN2.2 3660,4765 3701.05,4723.95 3831.05,4723.95 3910,4645 3910,4580 3952.4,4537.6 D2.3 4017.4,4537.6 4030,4525 4030,4385 4100.4,4314.6 U1.39
VCC: CN8.1 CN9.1 CN10.1 D6.2 R31.1 | length 1447.6
  Top Layer w10: R31.1 5215.6,3440.6 5585.9,3810.9 CN8.1 ; D6.2 5744.05,4670.95 5880,4535 5880,4370 5786.6,4276.6 CN10.1
VCC1: D5.1 D6.1 H1.2 | length 2721.7
  Top Layer w10: D5.1@3429.05,4425 3429.05,4494.05 v1(3430,4495) ; H1.2 4710,4895 5585,4895 5625,4855 D6.1@5625,4799.05
  Bottom Layer w10: v1(3430,4495) 3430,4610 3535,4715 3535,4845 3605,4915 4550,4915 H1.2
VCUP: CN4.1 CN5.1 D5.2 R33.1 | length 1716.6
  Top Layer w10: D5.2@3300.9,4425 3275,4425 3270,4420 3270,4205 3360,4115 CN5.1 ; v1(4872.8,3808.44) R33.1@4918.68,3808.44
  Bottom Layer w10: CN4.1 3835,3730 4794.4,3730 v1(4872.8,3808.44)
X1_3: U1.5 X1.3 | length 88.7
  Top Layer w10: X1.3 4290.5,4042.3 U1.5
"": CN1.4 U1.1 U1.2 U1.6 U1.11 U1.15 U1.17 U1.18 U1.19 U1.20 U1.21 U1.22 U1.28 U1.40 U1.41 U4.4 U7.1 U7.2 U7.3 X1.1

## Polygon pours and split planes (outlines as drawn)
VCUP on Bottom Layer (solid, remove dead copper, pour order 0): 3380,4125 3381.67,4123.33 3379,4125
VCUP on Bottom Layer (solid, remove dead copper, pour order 1): 3379,4125 3370,4125 3355,4140
PGND on Top Layer (solid, remove dead copper, pour order 2): 5650,4210 5650,4385 5480,4550 5365,4550 5300,4430 5510,4235 5510,4210
PGND_IN on Top Layer (solid, remove dead copper, pour order 3): 5510,4020 5575,4085 5790,4085 5790,3930 5655,3930 5635,3950 5530,3950 5510,3970
PGND_OUT on Top Layer (solid, remove dead copper, pour order 4): 5510,4625 5670,4625 5700,4625 5795,4530 5795,4475 5760,4440 5620,4440 5510,4545 5510,4585
VCC on Top Layer (solid, remove dead copper, pour order 5): 5335,3940 5335,4000 5315,4020 5315,4065 5315,4150 5380,4200 5470,4200 5655,4200 5660,4205 5660,4280 5725,4345 5840,4345 5880,4305 5880,4210 5770,4100 5570,4100 5500,4030 5500,3955 5580,3890 5780,3890 5785,3755 5530,3755
PGND_CUP_IN on Top Layer (solid, remove dead copper, pour order 6): 3325,4330 3470,4330 3630,4170 3630,4110 3465,4110 3325,4255
PGND_CUP on Top Layer (solid, remove dead copper, pour order 7): 3490,4355 3490,4520 3625,4520 3635,4480 3635,4355
VCUP on Bottom Layer (solid, remove dead copper, pour order 8): 3345,4130 3440,4130 3485,4085 3760,3855 3765,3800 3745,3780 3560,3780 3295,4045
GND on Top Layer (hatched 45Degree grid 30 track 10, remove dead copper, pour order 9): 3005,5280 5995,5280 6070,5205 6070,3075 6030,3035 3000,3035
GND on Bottom Layer (hatched 45Degree grid 30 track 10, remove dead copper, pour order 10): 3075,5245 6065,5245 6140,5170 6140,3040 6100,3000 3070,3000

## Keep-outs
Board Outline Layer:
  lines w10 net "": 3230,3285 ccw(c3320,3285) 3320,3195 5845,3195 ccw(c5845,3285) 5935,3285 5935,4905 ccw(c5845,4905) 5845,4995 3320,4995 ccw(c3320,4905) 3230,4905 3230,3285

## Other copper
Top Layer:
  text "V3.4" at 3288.54,4657.13 h37.68

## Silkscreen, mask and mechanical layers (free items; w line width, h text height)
Mechanical Layer:
  circle w1 net "": c3355,3320 r65
  circle w1 net "": c3360,4865 r65
  circle w1 net "": c5805,4865 r65
  circle w1 net "": c5805,3320 r65
Mech6:
  lines w10 net "": 3235,3950 3475,3950 3475,4385 3235,4385 ; 5925,3695 5660,3695 5660,4590 5668.6,4590 5865,4590 5938.6,4590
